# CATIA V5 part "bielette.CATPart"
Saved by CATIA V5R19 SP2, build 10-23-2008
Part number: bielette
Bounding box of the stored display mesh (mm): x -50 to 50, y -49.97 to 549.97, z -50 to 50
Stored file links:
  C:\Users\matthieu\Desktop\IAO\modele_CAO\bielette.CATPart
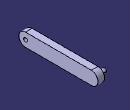
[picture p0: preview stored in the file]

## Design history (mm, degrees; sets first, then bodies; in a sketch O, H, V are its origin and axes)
Body1 (main body)
  Sketch1 on yz-plane, origin (0, 0, 0), H (0, 1, 0), V (0, 0, 1)
    construction line L1 (0, 0) -> (500, 0)
    line L2 (0, 50) -> (500, 50)
    line L3 (500, -50) -> (0, -50)
    arc A1 centre (500, 0) radius 50 from (500, 50) to (500, -50) cw
    arc A2 centre (0, 0) radius 50 from (0, -50) to (0, 50) cw
    circle A3 centre (0, 0) radius 15
    circle A4 centre (500, 0) radius 15
    distance L1 L2 = 50
    radius A3 = 15
    radius A4 = 15
    length L3 = 500
    horizontal: L1 H
    tangency: A1 L2, A2 L2, A1 L3, A2 L3
  MultiPad1: profile Sketch1, domains (length 50; length 50 / length 50; length 0)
